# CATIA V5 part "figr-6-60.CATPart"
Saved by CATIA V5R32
Part number: Part1
Bounding box of the stored display mesh (mm): x -50.648 to 50.648, y -72.183 to 72.183, z -40 to 40
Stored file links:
  D:\PROJECTS\Project 2022\CATIA V5 6R 2022\Resources\Part Files\c06_catia_v5_6r2022_prt\figr-6-60.CATPart
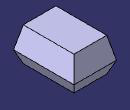
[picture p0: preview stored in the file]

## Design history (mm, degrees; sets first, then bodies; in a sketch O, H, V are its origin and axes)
Body1 (main body)
  Sketch1 on xy-plane, origin (0, 0, 0), H (1, 0, 0), V (0, 1, 0)
    line L1 (-50.6478, 72.1832) -> (50.6478, 72.1832)
    line L2 (50.6478, 72.1832) -> (50.6478, -72.1832)
    line L3 (50.6478, -72.1832) -> (-50.6478, -72.1832)
    line L4 (-50.6478, -72.1832) -> (-50.6478, 72.1832)
    axis line L5 (50.6478, -72.1832) -> (-50.6478, 72.1832)
    horizontal: L1 H, L3 H
    vertical: L2 V, L4 V
    midpoint: O L5
  Pad1: profile Sketch1, direction (0, 0, 1), length 40, mirrored extent
  Draft1: Angle 30, Neutral xy-plane, PullDir (0, 0, 1), SupportToDraft (face of Pad1; face of Pad1)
